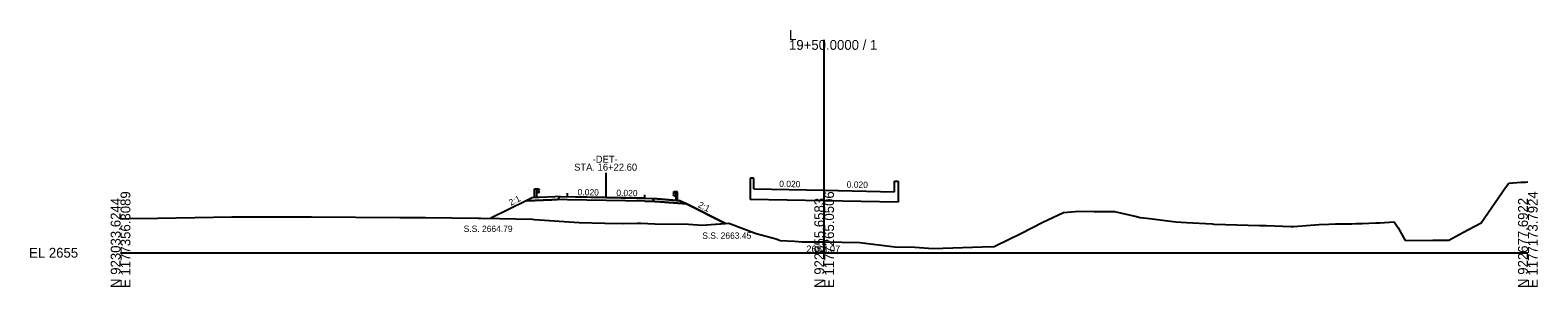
# Model space of a CAD drawing. Extents: x -26 to 1403, y -10 to 9563.
# Drawn here: x -25.7 to 402.8, y 9490.3 to 9563.3 of the extents above; entities that cross this region are included whole.
import ezdxf

# ---------------------------------------------------------------- set-up
doc = ezdxf.new("R2010")
doc.units = 0
for name, color, linetype in [('Exist Cross Section Cell', 7, 'Continuous'), ('Exist XS Center Line Elevation Label', 7, 'Continuous'), ('Exist XS Ground Line', 7, 'Continuous'), ('Prop XS Bridge', 7, 'Continuous'), ('Prop XS Dump Level', 7, 'Continuous'), ('Prop XS Earthwork Shape', 7, 'Continuous'), ('Prop XS EOT Tick Mark', 7, 'Continuous'), ('Prop XS Finish Grade', 7, 'Continuous'), ('Prop XS Finish Grade Earthwork', 7, 'Continuous'), ('Prop XS Finish Grade Pavement', 7, 'Continuous'), ('Prop XS Guardrail', 7, 'Continuous'), ('Prop XS Pvmt Edge Slope', 7, 'Continuous'), ('Prop XS SE Text', 7, 'Continuous'), ('Prop XS Shoulder Borrow Shape', 7, 'Continuous'), ('Prop XS Side Slope Text', 7, 'Continuous'), ('Prop XS SS Elevation Text', 7, 'Continuous'), ('Prop XS Subgrade Earthwork', 7, 'Continuous'), ('Prop XS Vertical Lines', 7, 'Continuous')]:
    doc.layers.add(name, color=color, linetype=linetype)

msp = doc.modelspace()

# ---------------------------------------------------------------- linework, layer by layer
at = {"layer": 'Exist Cross Section Cell'}
for p, q in [((200, 9500), (200, 9560.52)), ((0, 9500), (200, 9500)), ((200, 9500), (400, 9500))]:
    msp.add_line(p, q, dxfattribs=at)
at = {"layer": 'Exist XS Ground Line'}
for p, q in [((386.7, 9508.55), (393.6, 9518.53)), ((393.6, 9518.53), (394.55, 9519.84)), ((394.55, 9519.84), (398.12, 9520.04)), ((398.12, 9520.04), (398.69, 9520.07)), ((398.69, 9520.07), (399.29, 9520.11)), ((399.29, 9520.11), (400, 9520.17)), ((0, 9509.7), (2.41, 9509.73)), ((2.41, 9509.73), (10.63, 9509.81)), ((10.63, 9509.81), (31.62, 9510.19)), ((31.62, 9510.19), (47.73, 9510.23)), ((47.73, 9510.23), (50.45, 9510.24)), ((50.45, 9510.24), (54.23, 9510.24)), ((54.23, 9510.24), (79.39, 9510.04)), ((79.39, 9510.04), (86.67, 9510.05)), ((86.67, 9510.05), (101.67, 9509.87)), ((101.67, 9509.87), (102.37, 9509.86)), ((102.37, 9509.86), (107.72, 9509.74)), ((107.72, 9509.74), (116.96, 9509.52)), ((116.96, 9509.52), (117.66, 9509.51)), ((117.66, 9509.51), (130.37, 9508.64)), ((262.13, 9508.75), (268.01, 9511.45)), ((268.01, 9511.45), (271.37, 9511.75)), ((271.37, 9511.75), (272.24, 9511.82)), ((272.24, 9511.82), (276.75, 9511.76)), ((276.75, 9511.76), (282.48, 9511.75)), ((282.48, 9511.75), (288.73, 9510.36)), ((288.73, 9510.36), (289.8, 9510.07)), ((289.8, 9510.07), (291.66, 9509.84)), ((291.66, 9509.84), (299.99, 9508.82)), ((130.37, 9508.64), (137.67, 9508.38)), ((137.67, 9508.38), (142.95, 9508.31)), ((142.95, 9508.31), (146.8, 9508.41)), ((146.8, 9508.41), (147.92, 9508.39)), ((147.92, 9508.39), (151.89, 9508.28)), ((151.89, 9508.28), (161.44, 9508.11)), ((161.44, 9508.11), (165.19, 9507.87)), ((165.19, 9507.87), (172.93, 9508.41)), ((172.93, 9508.41), (180.68, 9505.53)), ((180.68, 9505.53), (186.34, 9503.95)), ((248.88, 9502.05), (255.88, 9505.45)), ((255.88, 9505.45), (262.13, 9508.75)), ((299.99, 9508.82), (303.01, 9508.58)), ((303.01, 9508.58), (310.25, 9508.2)), ((310.25, 9508.2), (310.77, 9508.17)), ((310.77, 9508.17), (314.09, 9508.08)), ((314.09, 9508.08), (323.77, 9507.78)), ((323.77, 9507.78), (325.62, 9507.74)), ((325.62, 9507.74), (332.76, 9507.46)), ((332.76, 9507.46), (333.43, 9507.5)), ((333.43, 9507.5), (340.71, 9508.08)), ((340.71, 9508.08), (343.4, 9508.14)), ((343.4, 9508.14), (345.32, 9508.22)), ((345.32, 9508.22), (347.49, 9508.22)), ((347.49, 9508.22), (349.94, 9508.22)), ((349.94, 9508.22), (351.1, 9508.34)), ((351.1, 9508.34), (352.87, 9508.35)), ((352.87, 9508.35), (356.76, 9508.49)), ((356.76, 9508.49), (357.89, 9508.53)), ((357.89, 9508.53), (362.03, 9508.79)), ((362.03, 9508.79), (363.14, 9507.05)), ((363.14, 9507.05), (365.16, 9503.53)), ((379.67, 9504.69), (381.51, 9505.8)), ((381.51, 9505.8), (386.7, 9508.55)), ((186.34, 9503.95), (187.49, 9503.54)), ((187.49, 9503.54), (191.58, 9503.27)), ((191.58, 9503.27), (193.71, 9503.14)), ((193.71, 9503.14), (200, 9503.07)), ((200, 9503.07), (210.11, 9502.95)), ((210.11, 9502.95), (220.1, 9501.7)), ((220.1, 9501.7), (225.72, 9501.6)), ((225.72, 9501.6), (230.98, 9501.2)), ((230.98, 9501.2), (244.92, 9501.66)), ((244.92, 9501.66), (248.33, 9501.74)), ((248.33, 9501.74), (248.88, 9502.05)), ((365.16, 9503.53), (372.99, 9503.55)), ((372.99, 9503.55), (377.55, 9503.56)), ((377.55, 9503.56), (379.67, 9504.69))]:
    msp.add_line(p, q, dxfattribs=at)
at = {"layer": 'Prop XS Bridge'}
for p, q in [((179, 9521.18), (179, 9518.18)), ((180, 9521.18), (179, 9521.18)), ((179, 9518.17), (179, 9515.17)), ((180, 9518.18), (180, 9521.18)), ((180, 9518.18), (200, 9517.78)), ((200, 9517.78), (220, 9517.38)), ((220, 9520.4), (221, 9520.4)), ((220, 9517.38), (220, 9520.38)), ((221, 9520.4), (221, 9517.4)), ((221, 9514.4), (179, 9515.17)), ((221, 9517.4), (221, 9514.4))]:
    msp.add_line(p, q, dxfattribs=at)
at = {"layer": 'Prop XS Dump Level'}
for p, q in [((125, 9515.97), (138, 9515.71)), ((138, 9515.71), (127, 9515.93)), ((149, 9515.49), (138, 9515.71)), ((138, 9515.71), (151, 9515.45))]:
    msp.add_line(p, q, dxfattribs=at)
at = {"layer": 'Prop XS Earthwork Shape'}
for p, q in [((115.29, 9514.8), (105.28, 9509.8)), ((122.61, 9515.09), (115.29, 9514.8)), ((124.18, 9515.16), (122.61, 9515.09)), ((127, 9515.1), (124.18, 9515.16)), ((138, 9514.88), (127, 9515.1)), ((149, 9514.66), (138, 9514.88)), ((151.85, 9514.6), (149, 9514.66)), ((153.42, 9514.48), (151.85, 9514.6)), ((160.87, 9513.88), (153.42, 9514.48)), ((171.95, 9508.34), (160.87, 9513.88)), ((105.28, 9509.8), (107.72, 9509.74)), ((107.72, 9509.74), (116.96, 9509.52)), ((116.96, 9509.52), (117.66, 9509.51)), ((117.66, 9509.51), (130.37, 9508.64)), ((130.37, 9508.64), (137.67, 9508.38)), ((137.67, 9508.38), (142.95, 9508.31)), ((142.95, 9508.31), (146.8, 9508.41)), ((146.8, 9508.41), (147.92, 9508.39)), ((147.92, 9508.39), (151.89, 9508.28)), ((151.89, 9508.28), (161.44, 9508.11)), ((161.44, 9508.11), (165.19, 9507.87)), ((165.19, 9507.87), (171.95, 9508.34))]:
    msp.add_line(p, q, dxfattribs=at)
at = {"layer": 'Prop XS EOT Tick Mark'}
for p, q in [((127, 9515.93), (127, 9516.93)), ((149, 9515.49), (149, 9516.49))]:
    msp.add_line(p, q, dxfattribs=at)
at = {"layer": 'Prop XS Finish Grade'}
for p, q in [((125, 9515.97), (123.43, 9515.91)), ((151, 9515.45), (152.57, 9515.33))]:
    msp.add_line(p, q, dxfattribs=at)
at = {"layer": 'Prop XS Finish Grade Earthwork'}
for p, q in [((115.29, 9514.8), (105.28, 9509.8)), ((117, 9515.65), (115.29, 9514.8)), ((119, 9515.73), (117, 9515.65)), ((123.43, 9515.91), (119, 9515.73)), ((152.57, 9515.33), (157.01, 9514.97)), ((157.01, 9514.97), (159.01, 9514.81)), ((159.01, 9514.81), (160.87, 9513.88)), ((160.87, 9513.88), (171.95, 9508.34))]:
    msp.add_line(p, q, dxfattribs=at)
at = {"layer": 'Prop XS Finish Grade Pavement'}
for p, q in [((125, 9515.97), (138, 9515.71)), ((138, 9515.71), (151, 9515.45))]:
    msp.add_line(p, q, dxfattribs=at)
at = {"layer": 'Prop XS Guardrail'}
for p, q in [((117.68, 9518.18), (118.18, 9518.18)), ((117.68, 9515.68), (117.68, 9518.18)), ((118.18, 9518.18), (118.68, 9518.18)), ((118.18, 9518.18), (118.18, 9515.68)), ((118.68, 9518.18), (118.97, 9517.98)), ((118.97, 9517.86), (118.68, 9517.66)), ((118.97, 9517.98), (119, 9517.92)), ((119, 9517.92), (118.97, 9517.86)), ((118.68, 9517.05), (118.18, 9517.05)), ((118.68, 9517.66), (118.68, 9517.57)), ((118.68, 9517.57), (118.97, 9517.37)), ((118.97, 9517.25), (118.68, 9517.05)), ((118.97, 9517.37), (119, 9517.31)), ((119, 9517.31), (118.97, 9517.25)), ((157.03, 9517.17), (157, 9517.11)), ((157, 9517.11), (157.03, 9517.05)), ((157.03, 9516.55), (157, 9516.49)), ((157, 9516.49), (157.03, 9516.43)), ((157.32, 9517.37), (157.03, 9517.17)), ((157.03, 9517.05), (157.32, 9516.85)), ((157.32, 9516.75), (157.03, 9516.55)), ((157.03, 9516.43), (157.32, 9516.23)), ((157.82, 9517.37), (157.32, 9517.37)), ((157.32, 9516.85), (157.32, 9516.75)), ((157.32, 9516.23), (157.82, 9516.23)), ((158.32, 9517.37), (157.82, 9517.37)), ((157.82, 9517.37), (157.82, 9514.87)), ((158.32, 9514.87), (158.32, 9517.37))]:
    msp.add_line(p, q, dxfattribs=at)
at = {"layer": 'Prop XS Pvmt Edge Slope'}
for p, q in [((125, 9515.97), (124.18, 9515.16)), ((151, 9515.45), (151.85, 9514.6))]:
    msp.add_line(p, q, dxfattribs=at)
at = {"layer": 'Prop XS Shoulder Borrow Shape'}
for p, q in [((117, 9515.65), (115.29, 9514.8)), ((115.29, 9514.8), (122.61, 9515.09)), ((117.68, 9515.68), (117, 9515.65)), ((123.43, 9515.91), (119, 9515.73)), ((122.61, 9515.09), (124.18, 9515.16)), ((125, 9515.97), (123.43, 9515.91)), ((124.18, 9515.16), (125, 9515.97)), ((152.57, 9515.33), (151, 9515.45)), ((151, 9515.45), (151.85, 9514.6)), ((151.85, 9514.6), (153.42, 9514.48)), ((157.01, 9514.97), (152.57, 9515.33)), ((153.42, 9514.48), (160.87, 9513.88)), ((157.82, 9514.91), (157.01, 9514.97)), ((160.87, 9513.88), (159.01, 9514.81))]:
    msp.add_line(p, q, dxfattribs=at)
for points in [[(119, 9515.73), (118.18, 9515.7), (117.68, 9515.68)], [(159.01, 9514.81), (158.32, 9514.87), (157.82, 9514.91)]]:
    msp.add_lwpolyline(points, dxfattribs=at)
at = {"layer": 'Prop XS Subgrade Earthwork'}
for p, q in [((122.61, 9515.09), (115.29, 9514.8)), ((124.18, 9515.16), (122.61, 9515.09)), ((127, 9515.1), (124.18, 9515.16)), ((138, 9514.88), (127, 9515.1)), ((149, 9514.66), (138, 9514.88)), ((149, 9514.66), (151.85, 9514.6)), ((151.85, 9514.6), (153.42, 9514.48)), ((153.42, 9514.48), (160.87, 9513.88))]:
    msp.add_line(p, q, dxfattribs=at)
at = {"layer": 'Prop XS Vertical Lines'}
msp.add_line((138, 9515.71), (138, 9522.71), dxfattribs=at)

# ---------------------------------------------------------------- texts
at = {"layer": 'Exist Cross Section Cell'}
for s, p in [('19+50.0000 / 1', (190, 9557.72)), ('L', (190, 9560.52)), ('EL 2655', (-26, 9498.6))]:
    msp.add_text(s, height=2.8, dxfattribs=at).set_placement(p)
for s, p in [('N 923033.6244', (0, 9490)), ('E 1177356.3089', (2.8, 9490)), ('N 922855.6583', (200, 9490)), ('E 1177265.0506', (202.8, 9490)), ('N 922677.6922', (400, 9490)), ('E 1177173.7924', (402.8, 9490))]:
    msp.add_text(s, height=2.8, rotation=90, dxfattribs=at).set_placement(p)
at = {"layer": 'Exist XS Center Line Elevation Label'}
msp.add_text('2658.07', height=2, dxfattribs=at).set_placement((194.91, 9500.07))
at = {"layer": 'Prop XS Dump Level'}
for p in [(119, 9515.57), (157, 9514.93)]:
    msp.add_text('Case1', height=0.04, dxfattribs=at).set_placement(p)
at = {"layer": 'Prop XS SE Text'}
for p in [(129.91, 9516.38), (140.91, 9516.16), (187.2, 9518.74), (206.39, 9518.54)]:
    msp.add_text('0.020', height=1.8, rotation=358.8542, dxfattribs=at).set_placement(p)
at = {"layer": 'Prop XS Side Slope Text'}
for rotation, p in [(26.5651, (110.91, 9513.33)), (333.4349, (163.98, 9513.06))]:
    msp.add_text('2:1', height=1.8, rotation=rotation, dxfattribs=at).set_placement(p)
at = {"layer": 'Prop XS SS Elevation Text'}
for s, p in [('S.S. 2664.79', (97.52, 9505.93)), ('S.S. 2663.45', (165.35, 9503.98))]:
    msp.add_text(s, height=1.8, dxfattribs=at).set_placement(p)
at = {"layer": 'Prop XS Vertical Lines'}
for s, p in [('-DET-', (134.19, 9525.6)), ('STA. 16+22.60', (128.91, 9523.35))]:
    msp.add_text(s, height=2, dxfattribs=at).set_placement(p)

doc.saveas('drawing.dxf')
